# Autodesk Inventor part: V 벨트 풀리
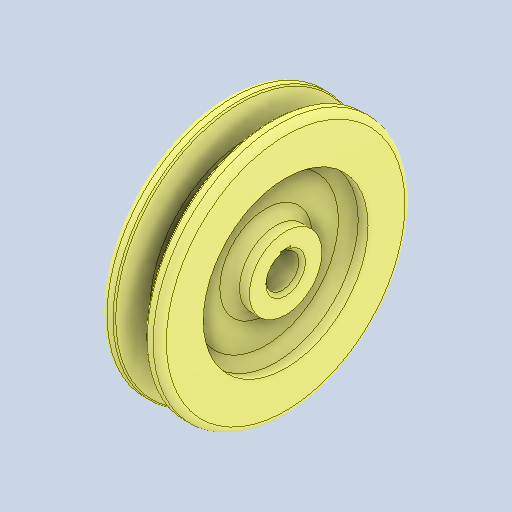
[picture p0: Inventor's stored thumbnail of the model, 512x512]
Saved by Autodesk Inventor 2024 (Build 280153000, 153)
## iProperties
Created: 2025-10
Part Number: V 벨트 풀리
Material: 강철, 주조
Document SubType Name: Modeling
Designer: EDU03
Density: 7.85 g/cm^3
Appearance: 기본값
Author: jhkim
Sending System: Autodesk Inventor 2026
Preprocessor: ST-DEVELOPER v20.1
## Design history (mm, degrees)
feature "솔리드1"
node "솔리드2"
